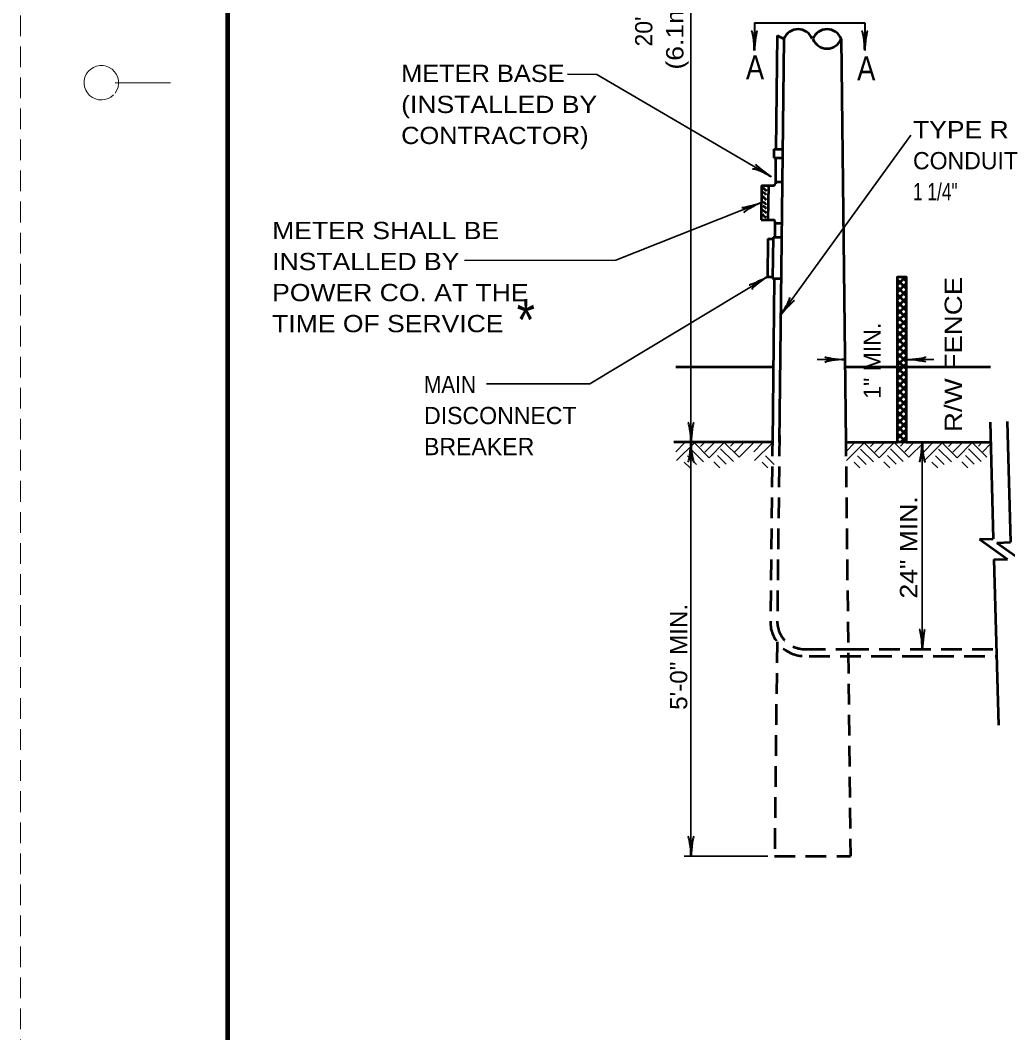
# Model space of a CAD drawing. Extents: x -68 to 612, y -58 to 382.
# Drawn here: x -67.7 to 75.5, y 90.7 to 237.5 of the extents above; entities that cross this region are included whole.
import ezdxf
from ezdxf.enums import TextEntityAlignment as Align

# ---------------------------------------------------------------- set-up
doc = ezdxf.new("R2010")
doc.units = 0
doc.linetypes.add('MEDIUM_DASHED', pattern=[4.5, 3, -1.5])
doc.layers.add('1', color=7, linetype='Continuous', lineweight=53)
doc.layers.add('61', color=7, linetype='Continuous', lineweight=35)

msp = doc.modelspace()

# ---------------------------------------------------------------- linework, layer by layer
at = {"layer": '1', "linetype": 'MEDIUM_DASHED', "lineweight": 13}
msp.add_line((-67.611, 382.166), (-67.671, -57.874), dxfattribs=at)
at = {"layer": '1', "lineweight": 40}
for p, q in [((38.759, 237.075), (54.759, 237.075)), ((38.759, 237.075), (38.759, 233.075)), ((54.759, 237.075), (54.759, 233.075))]:
    msp.add_line(p, q, dxfattribs=at)
at = {"layer": '1'}
for p, q in [((42.041, 235.275), (41.854, 218.775)), ((42.041, 235.275), (43.035, 234.764)), ((43.035, 234.764), (42.371, 176.275)), ((51.342, 234.764), (52.007, 176.275)), ((41.587, 218.775), (42.854, 218.775)), ((41.587, 218.775), (41.587, 217.525)), ((41.587, 217.525), (42.854, 217.525)), ((41.84, 217.525), (41.797, 213.773)), ((39.8, 213.525), (39.731, 208.525)), ((39.8, 213.525), (41.547, 213.525)), ((40.8, 213.512), (40.731, 208.512)), ((41.8, 214.025), (42.8, 214.025)), ((39.731, 208.525), (41.484, 208.525)), ((41.734, 208.273), (41.709, 206.025)), ((41.731, 208.025), (42.732, 208.025)), ((40.706, 205.784), (40.643, 200.284)), ((40.706, 205.784), (41.456, 205.784)), ((41.459, 206.025), (41.391, 200.025)), ((41.459, 206.025), (42.709, 206.025)), ((40.643, 200.284), (41.393, 200.284)), ((41.641, 200.025), (41.371, 176.275)), ((41.391, 200.025), (42.641, 200.025)), ((59.507, 200.18), (59.603, 200.275)), ((59.507, 199.119), (60.663, 200.275)), ((60.757, 198.571), (59.507, 199.821)), ((60.757, 199.632), (60.113, 200.275)), ((59.507, 198.058), (60.757, 199.308)), ((60.757, 197.511), (59.507, 198.761)), ((59.507, 196.998), (60.757, 198.248)), ((60.757, 196.45), (59.507, 197.7)), ((59.507, 195.937), (60.757, 197.187)), ((60.757, 195.389), (59.507, 196.639)), ((59.507, 194.876), (60.757, 196.126)), ((60.757, 194.329), (59.507, 195.579)), ((59.507, 193.816), (60.757, 195.066)), ((60.757, 193.268), (59.507, 194.518)), ((59.507, 192.755), (60.757, 194.005)), ((60.757, 192.207), (59.507, 193.457)), ((59.507, 191.694), (60.757, 192.944)), ((60.757, 191.147), (59.507, 192.397)), ((59.507, 190.634), (60.757, 191.884)), ((60.757, 190.086), (59.507, 191.336)), ((59.507, 189.573), (60.757, 190.823)), ((60.757, 189.025), (59.507, 190.275)), ((59.507, 188.512), (60.757, 189.762)), ((60.757, 187.965), (59.507, 189.215)), ((59.507, 187.452), (60.757, 188.702)), ((60.757, 186.904), (59.507, 188.154)), ((27.371, 187.207), (41.371, 187.207)), ((52.007, 187.207), (73.007, 187.207)), ((59.507, 186.391), (60.757, 187.641)), ((60.757, 185.843), (59.507, 187.093)), ((59.507, 185.33), (60.757, 186.58)), ((60.757, 184.783), (59.507, 186.033)), ((59.507, 184.27), (60.757, 185.52)), ((60.757, 183.722), (59.507, 184.972)), ((59.507, 183.209), (60.757, 184.459)), ((60.757, 182.661), (59.507, 183.911)), ((59.507, 182.148), (60.757, 183.398)), ((60.757, 181.601), (59.507, 182.851)), ((59.507, 181.088), (60.757, 182.338)), ((60.757, 180.54), (59.507, 181.79)), ((59.507, 180.027), (60.757, 181.277)), ((60.757, 179.479), (59.507, 180.729)), ((59.507, 178.966), (60.757, 180.216)), ((60.757, 178.419), (59.507, 179.669)), ((59.507, 177.906), (60.757, 179.156)), ((72.926, 179.206), (73.392, 162.275)), ((75.424, 179.274), (75.906, 161.775)), ((60.757, 177.358), (59.507, 178.608)), ((59.507, 176.845), (60.757, 178.095)), ((41.371, 176.275), (27.08, 176.275)), ((52.007, 176.275), (59.507, 176.275)), ((60.757, 176.297), (59.507, 177.547)), ((59.718, 176.275), (59.507, 176.487)), ((59.998, 176.275), (60.757, 177.034)), ((60.757, 176.275), (73.007, 176.275)), ((71.393, 162.22), (73.392, 162.275)), ((71.393, 162.22), (75.474, 159.331)), ((73.906, 161.72), (75.906, 161.775)), ((73.906, 161.72), (77.987, 158.831)), ((73.474, 159.276), (75.474, 159.331)), ((73.474, 159.276), (74.134, 135.279))]:
    msp.add_line(p, q, dxfattribs=at)
at = {"layer": '1', "lineweight": 35}
for p, q in [((15.917, 229.62), (11.684, 229.662)), ((41.2, 214.792), (15.917, 229.62)), ((42.553, 194.707), (61.443, 220.796)), ((39.766, 211.025), (18.659, 202.705)), ((18.659, 202.705), (-3.248, 202.655)), ((40.643, 200.284), (14.902, 184.728)), ((51.871, 188.275), (47.871, 188.275)), ((64.757, 188.275), (60.757, 188.275)), ((14.902, 184.728), (-0.087, 184.728)), ((28.691, 176.235), (27.371, 174.915)), ((30.111, 176.235), (27.491, 173.615)), ((30.011, 176.235), (32.211, 174.035)), ((31.531, 176.235), (30.971, 175.655)), ((32.971, 176.235), (31.591, 174.855)), ((34.391, 176.235), (32.211, 174.035)), ((34.391, 176.235), (36.531, 174.095)), ((35.811, 176.235), (35.291, 175.715)), ((37.251, 176.235), (35.931, 174.915)), ((38.671, 176.235), (36.531, 174.095)), ((39.991, 176.235), (38.671, 174.915)), ((41.411, 176.235), (38.791, 173.615)), ((53.327, 176.235), (52.007, 174.915)), ((54.747, 176.235), (52.127, 173.615)), ((54.647, 176.235), (56.847, 174.035)), ((56.167, 176.235), (55.607, 175.655)), ((57.607, 176.235), (56.227, 174.855)), ((59.027, 176.235), (56.847, 174.035)), ((59.027, 176.235), (61.167, 174.095)), ((60.447, 176.235), (59.927, 175.715)), ((61.887, 176.235), (60.567, 174.915)), ((63.307, 176.235), (61.167, 174.095)), ((63.098, 146.275), (63.098, 176.275)), ((64.627, 176.235), (63.307, 174.915)), ((66.047, 176.235), (63.427, 173.615)), ((65.947, 176.235), (68.147, 174.035)), ((67.467, 176.235), (66.907, 175.655)), ((68.907, 176.235), (67.527, 174.855)), ((70.327, 176.235), (68.147, 174.035)), ((70.327, 176.235), (72.467, 174.095)), ((71.747, 176.235), (71.227, 175.715)), ((29.531, 175.275), (31.391, 173.435)), ((33.871, 175.335), (35.711, 173.495)), ((54.167, 175.275), (56.027, 173.435)), ((58.507, 175.335), (60.347, 173.495)), ((65.467, 175.275), (67.327, 173.435)), ((69.807, 175.335), (71.647, 173.495)), ((73.013, 176.061), (71.867, 174.915)), ((28.571, 173.395), (29.431, 172.555)), ((29.071, 174.315), (30.351, 173.035)), ((32.891, 173.455), (33.751, 172.595)), ((33.411, 174.375), (34.691, 173.095)), ((39.871, 173.395), (40.731, 172.555)), ((40.371, 174.315), (41.651, 173.035)), ((53.207, 173.395), (54.067, 172.555)), ((53.707, 174.315), (54.987, 173.035)), ((57.527, 173.455), (58.387, 172.595)), ((58.047, 174.375), (59.327, 173.095)), ((64.507, 173.395), (65.367, 172.555)), ((65.007, 174.315), (66.287, 173.035)), ((68.827, 173.455), (69.687, 172.595)), ((69.347, 174.375), (70.627, 173.095)), ((40.689, 116.264), (28.57, 116.264))]:
    msp.add_line(p, q, dxfattribs=at)
at = {"layer": '1', "linetype": 'MEDIUM_DASHED'}
for p, q in [((41.382, 177.275), (41.076, 150.332)), ((42.382, 177.264), (42.076, 150.321)), ((51.996, 177.264), (52.689, 116.264)), ((42.042, 147.321), (41.689, 116.264)), ((46.689, 145.275), (73.859, 145.275)), ((41.689, 116.264), (52.689, 116.264))]:
    msp.add_line(p, q, dxfattribs=at)
at = {"layer": '1', "lineweight": 35}
msp.add_lwpolyline([(29.57, 294.939), (29.57, 176.275), (29.57, 116.264)], dxfattribs=at)
at = {"layer": '1'}
for points in [[(39.962, 213.215), (40.217, 212.982), (40.514, 212.748)], [(39.94, 211.94), (40.153, 211.749), (40.344, 211.578), (40.472, 211.451)], [(39.962, 212.599), (40.302, 212.365), (40.408, 212.174)], [(39.898, 210.027), (40.132, 209.856), (40.28, 209.75), (40.429, 209.601), (40.45, 209.559)], [(39.962, 210.579), (40.365, 210.303), (40.408, 210.239), (40.472, 210.175)], [(39.983, 211.175), (40.28, 210.962), (40.408, 210.834), (40.472, 210.728)], [(39.94, 209.346), (40.089, 209.134), (40.174, 209.07), (40.344, 208.964), (40.472, 208.9)]]:
    msp.add_lwpolyline(points, dxfattribs=at)
msp.add_lwpolyline([(59.507, 176.275), (59.507, 200.275), (60.757, 200.275), (60.757, 176.275)], close=True, dxfattribs=at)
at = {"layer": '1', "linetype": 'MEDIUM_DASHED'}
msp.add_lwpolyline([(46.076, 146.275), (52.348, 146.275), (73.848, 146.275)], dxfattribs=at)
at = {"layer": '1'}
for centre, radius, start, end in [((45.087, 233.958), 2.204, 21.451, 158.54901), ((49.291, 233.958), 2.204, 21.451, 158.54901), ((49.291, 235.57), 2.204, 201.45099, 338.549), ((41.547, 213.775), 0.25, 270, 359.35213), ((41.484, 208.275), 0.25, 359.35538, 90)]:
    msp.add_arc(centre, radius, start, end, dxfattribs=at)
at = {"layer": '1', "linetype": 'MEDIUM_DASHED'}
for radius, start in [(5, 179.34915), (4, 179.34912)]:
    msp.add_arc((46.076, 150.275), radius, start, 270, dxfattribs=at)
at = {"layer": '1', "lineweight": 40}
for centre, major_axis, ratio, start_param, end_param in [((38.483, 234.167), (0.156, -1.786), 0.122415, 0.8963533, 3.1415927), ((38.483, 234.167), (0.156, -1.786), 0.122415, 0.8963533, 3.1415927), ((38.971, 234.196), (-0.176, -1.756), 0.07063, 3.1407148, 5.41811), ((38.971, 234.196), (-0.176, -1.756), 0.07063, 3.1407148, 5.41811), ((54.483, 234.167), (0.156, -1.786), 0.122415, 0.8963533, 3.1415927), ((54.483, 234.167), (0.156, -1.786), 0.122415, 0.8963533, 3.1415927), ((54.971, 234.196), (-0.176, -1.756), 0.07063, 3.1407148, 5.41811), ((54.971, 234.196), (-0.176, -1.756), 0.07063, 3.1407148, 5.41811), ((40.119, 215.105), (1.619, -0.769), 0.122415, 0.8963533, 3.1415927), ((40.119, 215.105), (1.619, -0.769), 0.122415, 0.8963533, 3.1415927), ((40.119, 215.105), (1.619, -0.769), 0.122415, 0.8963533, 3.1415927), ((40.34, 215.541), (-1.426, 1.04), 0.07063, 6.2823074, 8.5597026), ((40.34, 215.541), (-1.426, 1.04), 0.07063, 6.2823074, 8.5597026), ((40.34, 215.541), (-1.426, 1.04), 0.07063, 6.2823074, 8.5597026), ((38.646, 210.811), (1.698, 0.481), 0.07063, 3.1407148, 5.41811), ((38.646, 210.811), (1.698, 0.481), 0.07063, 3.1407148, 5.41811), ((38.852, 210.368), (1.604, 0.8), 0.122415, 0.8963533, 3.1415927), ((38.852, 210.368), (1.604, 0.8), 0.122415, 0.8963533, 3.1415927), ((39.575, 199.885), (1.594, 0.758), 0.07063, 3.1407148, 5.41811), ((39.575, 199.885), (1.594, 0.758), 0.07063, 3.1407148, 5.41811), ((39.852, 199.483), (1.448, 1.057), 0.122415, 0.8963533, 3.1415927), ((39.852, 199.483), (1.448, 1.057), 0.122415, 0.8963533, 3.1415927), ((42.969, 195.753), (-0.921, -1.538), 0.122415, 0.8963533, 3.1415927), ((43.381, 195.491), (-1.172, -1.32), 0.07063, 3.1407148, 5.41811), ((50.779, 187.999), (1.786, 0.156), 0.122415, 0.8963533, 3.1415927), ((50.779, 187.999), (1.786, 0.156), 0.122415, 0.8963533, 3.1415927), ((50.75, 188.487), (1.756, -0.176), 0.07063, 3.1407148, 5.41811), ((50.75, 188.487), (1.756, -0.176), 0.07063, 3.1407148, 5.41811), ((61.877, 188.064), (-1.756, 0.176), 0.07063, 3.1407148, 5.41811), ((61.877, 188.064), (-1.756, 0.176), 0.07063, 3.1407148, 5.41811), ((61.848, 188.552), (-1.786, -0.156), 0.122415, 0.8963533, 3.1415927), ((61.848, 188.552), (-1.786, -0.156), 0.122415, 0.8963533, 3.1415927), ((29.293, 177.367), (0.156, -1.786), 0.122415, 0.8963533, 3.1415927), ((29.781, 177.396), (-0.176, -1.756), 0.07063, 3.1407148, 5.41811), ((29.358, 175.155), (0.176, 1.756), 0.07063, 3.1407148, 5.41811), ((29.358, 175.155), (0.176, 1.756), 0.07063, 3.1407148, 5.41811), ((29.846, 175.184), (-0.156, 1.786), 0.122415, 0.8963533, 3.1415927), ((29.846, 175.184), (-0.156, 1.786), 0.122415, 0.8963533, 3.1415927), ((62.886, 175.155), (0.176, 1.756), 0.07063, 3.1407148, 5.41811), ((62.886, 175.155), (0.176, 1.756), 0.07063, 3.1407148, 5.41811), ((63.374, 175.184), (-0.156, 1.786), 0.122415, 0.8963533, 3.1415927), ((63.374, 175.184), (-0.156, 1.786), 0.122415, 0.8963533, 3.1415927), ((62.822, 147.367), (0.156, -1.786), 0.122415, 0.8963533, 3.1415927), ((62.822, 147.367), (0.156, -1.786), 0.122415, 0.8963533, 3.1415927), ((63.31, 147.396), (-0.176, -1.756), 0.07063, 3.1407148, 5.41811), ((63.31, 147.396), (-0.176, -1.756), 0.07063, 3.1407148, 5.41811), ((29.293, 117.355), (0.156, -1.786), 0.122415, 0.8963533, 3.1415927), ((29.293, 117.355), (0.156, -1.786), 0.122415, 0.8963533, 3.1415927), ((29.293, 117.355), (0.156, -1.786), 0.122415, 0.8963533, 3.1415927), ((29.781, 117.385), (-0.176, -1.756), 0.07063, 3.1407148, 5.41811), ((29.781, 117.385), (-0.176, -1.756), 0.07063, 3.1407148, 5.41811), ((29.781, 117.385), (-0.176, -1.756), 0.07063, 3.1407148, 5.41811)]:
    msp.add_ellipse(centre, major_axis=major_axis, ratio=ratio, start_param=start_param, end_param=end_param, dxfattribs=at)
at = {"layer": '61', "lineweight": 13}
msp.add_line((-53.911, 228.406), (-45.911, 228.406), dxfattribs=at)
at = {"layer": '61', "lineweight": 158}
msp.add_lwpolyline([(601.429, 372.166), (-37.611, 372.166), (-37.611, -47.854)], dxfattribs=at)
at = {"layer": '61', "lineweight": 13}
msp.add_arc((-55.914, 228.407), 2.5, 323.13009, 315.37577, dxfattribs=at)

# ---------------------------------------------------------------- texts
at = {"layer": '1', "width": 1.15}
msp.add_text('(6.1m MIN.', height=2.5, rotation=90, dxfattribs=at).set_placement((28.469, 239.825), align=Align.CENTER)
at = {"layer": '1'}
msp.add_text("20' MIN.", height=2.5, rotation=90, dxfattribs=at).set_placement((23.969, 239.825), align=Align.CENTER)
for s, height, width, p in [('A', 3.5, 0.85, (37.526, 228.88)), ('A', 3.5, 0.85, (53.651, 228.75)), ('METER BASE', 2.5, 1.1, (-12.448, 228.519)), ('(INSTALLED BY', 2.5, 1.15, (-12.448, 224.019)), ('CONTRACTOR) ', 2.5, 1.1, (-12.448, 219.519)), ('TYPE R', 2.5, 1.15, (61.752, 220.36)), ('1 1/4"', 2.5, 0.75, (61.752, 211.36)), ('METER SHALL BE', 2.5, 1.15, (-31.15, 205.738)), ('INSTALLED BY', 2.5, 1.15, (-31.15, 201.238)), ('POWER CO. AT THE', 2.5, 1.15, (-31.15, 196.738)), ('*', 6, 0.85, (4.293, 191.038)), ('TIME OF SERVICE', 2.5, 1.15, (-31.15, 192.238)), ('MAIN', 2.5, 0.9, (-9.129, 183.408))]:
    msp.add_text(s, height=height, dxfattribs=dict(at, width=width)).set_placement(p)
for s, p in [('CONDUIT', (61.752, 215.86)), ('DISCONNECT', (-9.129, 178.908)), ('BREAKER', (-9.129, 174.408))]:
    msp.add_text(s, height=2.5, dxfattribs=at).set_placement(p)
for s, width, p in [('R/W FENCE', 1.2, (68.847, 177.761)), ('24" MIN.', 1.15, (62.361, 153.621)), ('5\'-0" MIN.', 1.05, (29.029, 137.478))]:
    msp.add_text(s, height=2.5, rotation=90, dxfattribs=dict(at, width=width)).set_placement(p)
msp.add_text('1" MIN.', height=2.5, rotation=90, dxfattribs=at).set_placement((57.082, 182.589))

doc.saveas('drawing.dxf')
